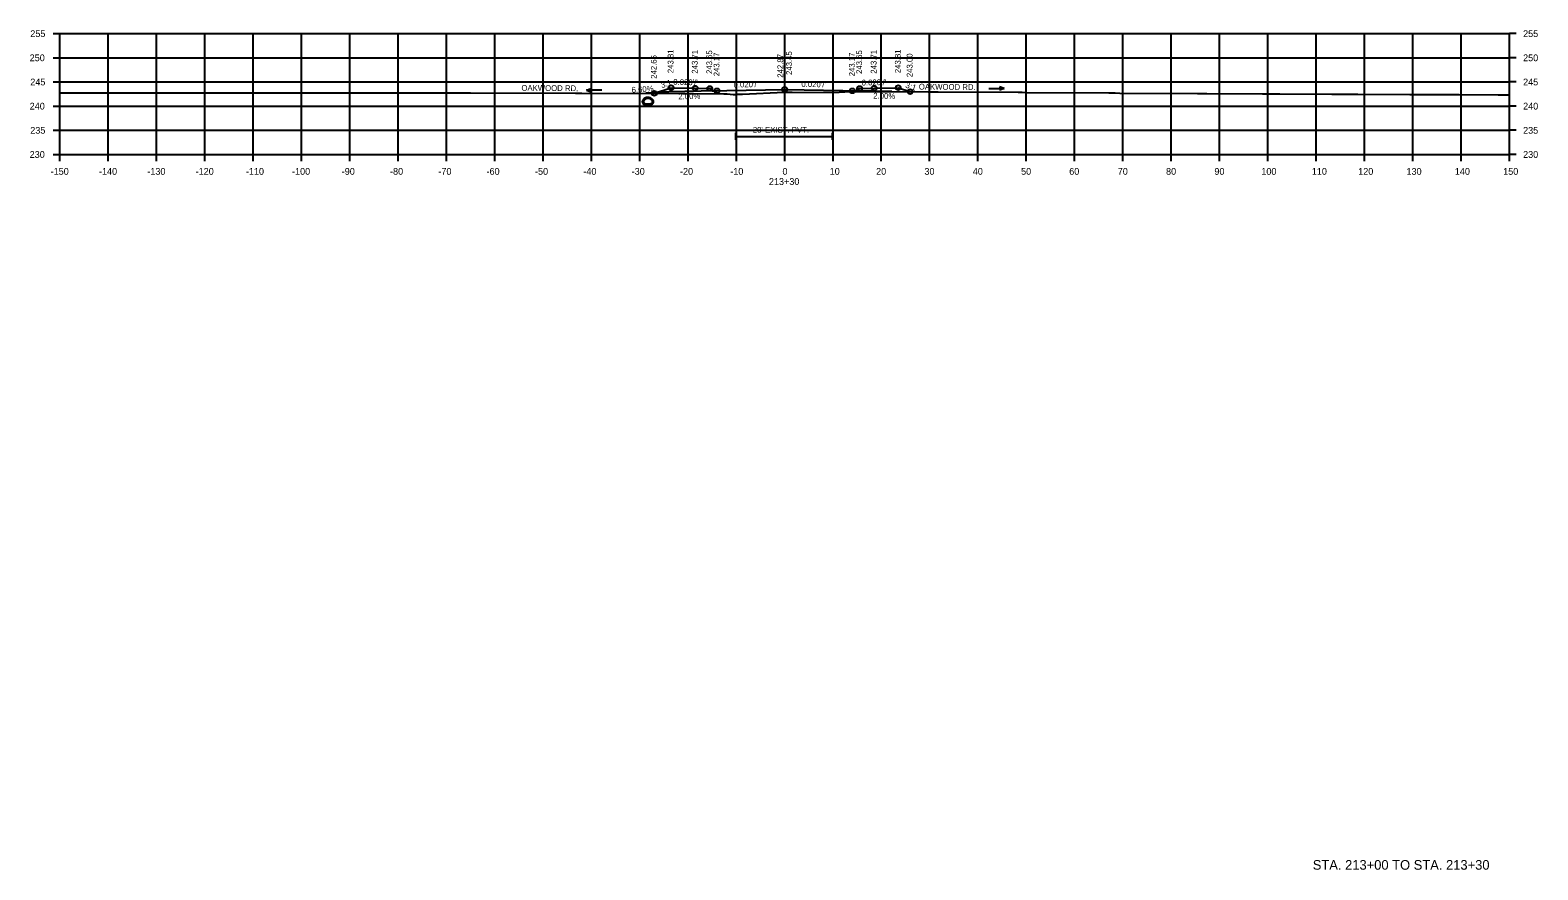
# Model space of a CAD drawing. Extents: x 1369627 to 1374022, y 380035 to 398173.
# Drawn here: x 1372730.1 to 1373042.1, y 383043.5 to 383217.3 of the extents above; entities that cross this region are included whole.
import ezdxf

# ---------------------------------------------------------------- set-up
doc = ezdxf.new("R2010")
doc.units = 0
for name, color, linetype in [('Default', 7, 'Continuous'), ('R_Alt Surface', 7, 'Continuous'), ('R_Axis', 7, 'Continuous'), ('R_Axis Annot', 7, 'Continuous'), ('R_Draft', 7, 'Continuous'), ('R_Drive', 7, 'Continuous'), ('R_Exist Surface', 7, 'Continuous'), ('R_Fin Surface', 7, 'Continuous'), ('R_Grid', 7, 'Continuous'), ('R_No Plot', 7, 'Continuous'), ('R_Water', 7, 'Continuous'), ('R_Water Annot', 7, 'Continuous'), ('R_Xsect Elev', 7, 'Continuous'), ('R_Xsect Slope', 7, 'Continuous')]:
    doc.layers.add(name, color=color, linetype=linetype)

msp = doc.modelspace()

# ---------------------------------------------------------------- linework, layer by layer
at = {"layer": 'Default'}
for p, q in [((1372876.1, 383194.57), (1372876.1, 383196.07)), ((1372876.1, 383195.32), (1372896.1, 383195.32)), ((1372896.1, 383194.57), (1372896.1, 383196.07))]:
    msp.add_line(p, q, dxfattribs=at)
at = {"layer": 'R_Axis'}
for p, q in [((1372734.81, 383216.57), (1372736.21, 383216.57)), ((1372736.21, 383191.57), (1372736.21, 383216.57)), ((1373036.21, 383191.57), (1373036.21, 383216.57)), ((1373037.61, 383216.57), (1373036.21, 383216.57)), ((1372734.81, 383211.57), (1372736.21, 383211.57)), ((1373037.61, 383211.57), (1373036.21, 383211.57)), ((1372734.81, 383206.57), (1372736.21, 383206.57)), ((1373037.61, 383206.57), (1373036.21, 383206.57)), ((1372734.81, 383201.57), (1372736.21, 383201.57)), ((1373037.61, 383201.57), (1373036.21, 383201.57)), ((1372734.81, 383196.57), (1372736.21, 383196.57)), ((1373037.61, 383196.57), (1373036.21, 383196.57)), ((1372734.81, 383191.57), (1372736.21, 383191.57)), ((1372736.21, 383191.57), (1373036.21, 383191.57)), ((1372736.21, 383190.17), (1372736.21, 383191.57)), ((1372746.21, 383190.17), (1372746.21, 383191.57)), ((1372756.21, 383190.17), (1372756.21, 383191.57)), ((1372766.21, 383190.17), (1372766.21, 383191.57)), ((1372776.21, 383190.17), (1372776.21, 383191.57)), ((1372786.21, 383190.17), (1372786.21, 383191.57)), ((1372796.21, 383190.17), (1372796.21, 383191.57)), ((1372806.21, 383190.17), (1372806.21, 383191.57)), ((1372816.21, 383190.17), (1372816.21, 383191.57)), ((1372826.21, 383190.17), (1372826.21, 383191.57)), ((1372836.21, 383190.17), (1372836.21, 383191.57)), ((1372846.21, 383190.17), (1372846.21, 383191.57)), ((1372856.21, 383190.17), (1372856.21, 383191.57)), ((1372866.21, 383190.17), (1372866.21, 383191.57)), ((1372876.21, 383190.17), (1372876.21, 383191.57)), ((1372886.21, 383190.17), (1372886.21, 383191.57)), ((1372896.21, 383190.17), (1372896.21, 383191.57)), ((1372906.21, 383190.17), (1372906.21, 383191.57)), ((1372916.21, 383190.17), (1372916.21, 383191.57)), ((1372926.21, 383190.17), (1372926.21, 383191.57)), ((1372936.21, 383190.17), (1372936.21, 383191.57)), ((1372946.21, 383190.17), (1372946.21, 383191.57)), ((1372956.21, 383190.17), (1372956.21, 383191.57)), ((1372966.21, 383190.17), (1372966.21, 383191.57)), ((1372976.21, 383190.17), (1372976.21, 383191.57)), ((1372986.21, 383190.17), (1372986.21, 383191.57)), ((1372996.21, 383190.17), (1372996.21, 383191.57)), ((1373006.21, 383190.17), (1373006.21, 383191.57)), ((1373016.21, 383190.17), (1373016.21, 383191.57)), ((1373026.21, 383190.17), (1373026.21, 383191.57)), ((1373036.21, 383190.17), (1373036.21, 383191.57)), ((1373037.61, 383191.57), (1373036.21, 383191.57))]:
    msp.add_line(p, q, dxfattribs=at)
at = {"layer": 'R_Drive'}
for p, q in [((1372862.21, 383204.55), (1372857.45, 383204.23)), ((1372872.21, 383204.75), (1372862.21, 383204.55)), ((1372908.38, 383204.58), (1372901.21, 383204.73))]:
    msp.add_line(p, q, dxfattribs=at)
at = {"layer": 'R_Exist Surface'}
msp.add_lwpolyline([(1372736.21, 383204.34), (1372738.85, 383204.34), (1372740.52, 383204.35), (1372760.34, 383204.33), (1372761.22, 383204.33), (1372761.22, 383204.33), (1372782.47, 383204.31), (1372782.51, 383204.31), (1372788.65, 383204.31), (1372801.68, 383204.32), (1372801.84, 383204.32), (1372820.79, 383204.32), (1372821.19, 383204.32), (1372842.91, 383204.26), (1372844.27, 383204.27), (1372865.07, 383204.21), (1372867.32, 383204.22), (1372873.6, 383204.1), (1372874.28, 383204.09), (1372875.53, 383203.97), (1372875.96, 383203.98), (1372876.23, 383204), (1372876.3, 383204.02), (1372877.5, 383204.07), (1372886.12, 383204.45), (1372887.79, 383204.45), (1372896.4, 383204.39), (1372899.78, 383204.61), (1372915.91, 383204.56), (1372917.54, 383204.52), (1372917.69, 383204.52), (1372917.77, 383204.52), (1372917.96, 383204.51), (1372934.56, 383204.45), (1372934.79, 383204.45), (1372935.36, 383204.44), (1372936.16, 383204.42), (1372953.32, 383204.33), (1372953.78, 383204.32), (1372954.59, 383204.3), (1372955.58, 383204.29), (1372971.61, 383204.2), (1372972.12, 383204.19), (1372972.95, 383204.18), (1372973.56, 383204.18), (1372985.11, 383204.11), (1372986.41, 383204.1), (1372988.67, 383204.1), (1372999.43, 383204.03), (1373001.12, 383204.03), (1373004.78, 383204.03), (1373015.54, 383203.99), (1373025.79, 383203.95), (1373033.88, 383203.93), (1373036.21, 383203.93)], dxfattribs=at)
at = {"layer": 'R_Fin Surface'}
msp.add_lwpolyline([(1372859.23, 383204.23), (1372862.7, 383205.39), (1372867.7, 383205.29), (1372870.7, 383205.23), (1372871.2, 383205.23), (1372871.21, 383204.73), (1372872.21, 383204.75), (1372874.21, 383204.79), (1372886.21, 383205.03), (1372898.21, 383204.79), (1372900.21, 383204.75), (1372901.21, 383204.73), (1372901.22, 383205.23), (1372901.72, 383205.23), (1372904.72, 383205.29), (1372909.72, 383205.39), (1372912.17, 383204.57)], dxfattribs=at)
at = {"layer": 'R_Grid'}
for p, q in [((1372736.21, 383216.57), (1373036.21, 383216.57)), ((1372736.21, 383191.57), (1372736.21, 383216.57)), ((1372746.21, 383191.57), (1372746.21, 383216.57)), ((1372756.21, 383191.57), (1372756.21, 383216.57)), ((1372766.21, 383191.57), (1372766.21, 383216.57)), ((1372776.21, 383191.57), (1372776.21, 383216.57)), ((1372786.21, 383191.57), (1372786.21, 383216.57)), ((1372796.21, 383191.57), (1372796.21, 383216.57)), ((1372806.21, 383191.57), (1372806.21, 383216.57)), ((1372816.21, 383191.57), (1372816.21, 383216.57)), ((1372826.21, 383191.57), (1372826.21, 383216.57)), ((1372836.21, 383191.57), (1372836.21, 383216.57)), ((1372846.21, 383191.57), (1372846.21, 383216.57)), ((1372856.21, 383191.57), (1372856.21, 383216.57)), ((1372866.21, 383191.57), (1372866.21, 383216.57)), ((1372876.21, 383191.57), (1372876.21, 383216.57)), ((1372886.21, 383191.57), (1372886.21, 383216.57)), ((1372896.21, 383191.57), (1372896.21, 383216.57)), ((1372906.21, 383191.57), (1372906.21, 383216.57)), ((1372916.21, 383191.57), (1372916.21, 383216.57)), ((1372926.21, 383191.57), (1372926.21, 383216.57)), ((1372936.21, 383191.57), (1372936.21, 383216.57)), ((1372946.21, 383191.57), (1372946.21, 383216.57)), ((1372956.21, 383191.57), (1372956.21, 383216.57)), ((1372966.21, 383191.57), (1372966.21, 383216.57)), ((1372976.21, 383191.57), (1372976.21, 383216.57)), ((1372986.21, 383191.57), (1372986.21, 383216.57)), ((1372996.21, 383191.57), (1372996.21, 383216.57)), ((1373006.21, 383191.57), (1373006.21, 383216.57)), ((1373016.21, 383191.57), (1373016.21, 383216.57)), ((1373026.21, 383191.57), (1373026.21, 383216.57)), ((1373036.21, 383191.57), (1373036.21, 383216.57)), ((1372736.21, 383211.57), (1373036.21, 383211.57)), ((1372736.21, 383206.57), (1373036.21, 383206.57)), ((1372736.21, 383201.57), (1373036.21, 383201.57)), ((1372736.21, 383196.57), (1373036.21, 383196.57)), ((1372736.21, 383191.57), (1373036.21, 383191.57))]:
    msp.add_line(p, q, dxfattribs=at)
at = {"layer": 'R_No Plot'}
for centre in [(1372859.23, 383204.23), (1372862.7, 383205.39), (1372867.7, 383205.29), (1372870.7, 383205.23), (1372872.21, 383204.75), (1372886.21, 383205.03), (1372900.21, 383204.75), (1372901.72, 383205.23), (1372904.72, 383205.29), (1372909.72, 383205.39), (1372912.17, 383204.57)]:
    msp.add_circle(centre, 0.5, dxfattribs=at)
at = {"layer": 'R_Water'}
for centre, radius, start, end in [((1372857.4, 383202.52), 0.646, 136.3515, 253.9529), ((1372857.91, 383202.03), 1.35, 43.6485, 136.3515), ((1372857.4, 383202.52), 0.438, 136.3515, 253.9529), ((1372857.91, 383202.03), 1.15, 43.6485, 136.3515), ((1372857.91, 383204.31), 2.5, 253.9529, 286.0471), ((1372857.91, 383204.31), 2.29, 253.9529, 286.0471), ((1372858.42, 383202.52), 0.438, 286.0471, 43.6485), ((1372858.42, 383202.52), 0.646, 286.0471, 43.6485)]:
    msp.add_arc(centre, radius, start, end, dxfattribs=at)
at = {"layer": 'R_Water Annot'}
for p, q in [((1372845.21, 383204.85), (1372846.17, 383205.2)), ((1372848.35, 383204.85), (1372845.21, 383204.85)), ((1372845.21, 383204.85), (1372846.17, 383204.5)), ((1372928.46, 383205.25), (1372931.6, 383205.25)), ((1372931.6, 383205.25), (1372930.64, 383205.6)), ((1372931.6, 383205.25), (1372930.64, 383204.9))]:
    msp.add_line(p, q, dxfattribs=at)
at = {"layer": 'R_Xsect Elev'}
msp.add_line((1372886.21, 383204.45), (1372886.21, 383214.45), dxfattribs=at)

# ---------------------------------------------------------------- texts
at = {"layer": 'R_Alt Surface'}
for p in [(1372831.73, 383204.75), (1372913.96, 383205)]:
    msp.add_text('OAKWOOD RD.', height=1.2, rotation=359.5795, dxfattribs=at).set_placement(p)
at = {"layer": 'R_Axis Annot'}
for s, height, p in [('255', 1.4, (1372730.1, 383215.87)), ('255', 1.4, (1373039.01, 383215.87)), ('250', 1.4, (1372729.98, 383210.87)), ('250', 1.4, (1373039.01, 383210.87)), ('245', 1.4, (1372730.1, 383205.87)), ('245', 1.4, (1373039.01, 383205.87)), ('240', 1.4, (1372729.98, 383200.87)), ('240', 1.4, (1373039.01, 383200.87)), ('235', 1.4, (1372730.1, 383195.87)), ("20' EXIST. PVT.", 1.2, (1372879.61, 383196.07)), ('235', 1.4, (1373039.01, 383195.87)), ('230', 1.4, (1372729.98, 383190.87)), ('230', 1.4, (1373039.01, 383190.87)), ('-150', 1.4, (1372734.32, 383187.37)), ('-140', 1.4, (1372744.32, 383187.37)), ('-130', 1.4, (1372754.32, 383187.37)), ('-120', 1.4, (1372764.32, 383187.37)), ('-110', 1.4, (1372774.72, 383187.37)), ('-100', 1.4, (1372784.27, 383187.37)), ('-90', 1.4, (1372794.55, 383187.37)), ('-80', 1.4, (1372804.55, 383187.37)), ('-70', 1.4, (1372814.55, 383187.37)), ('-60', 1.4, (1372824.52, 383187.37)), ('-50', 1.4, (1372834.55, 383187.37)), ('-40', 1.4, (1372844.55, 383187.37)), ('-30', 1.4, (1372854.55, 383187.37)), ('-20', 1.4, (1372864.55, 383187.37)), ('-10', 1.4, (1372874.95, 383187.37)), ('213+30', 1.4, (1372882.95, 383185.27)), ('0', 1.4, (1372885.75, 383187.37)), ('10', 1.4, (1372895.52, 383187.37)), ('20', 1.4, (1372905.13, 383187.37)), ('30', 1.4, (1372915.13, 383187.37)), ('40', 1.4, (1372925.13, 383187.37)), ('50', 1.4, (1372935.13, 383187.37)), ('60', 1.4, (1372945.09, 383187.37)), ('70', 1.4, (1372955.13, 383187.37)), ('80', 1.4, (1372965.13, 383187.37)), ('90', 1.4, (1372975.13, 383187.37)), ('100', 1.4, (1372984.84, 383187.37)), ('110', 1.4, (1372995.29, 383187.37)), ('120', 1.4, (1373004.89, 383187.37)), ('130', 1.4, (1373014.89, 383187.37)), ('140', 1.4, (1373024.89, 383187.37)), ('150', 1.4, (1373034.89, 383187.37))]:
    msp.add_text(s, height=height, dxfattribs=at).set_placement(p)
at = {"layer": 'R_Draft'}
msp.add_text('STA. 213+00 TO STA. 213+30', height=2, dxfattribs=at).set_placement((1372995.49, 383043.57))
at = {"layer": 'R_Xsect Elev'}
for s, rotation, p in [('242.65', 90, (1372859.73, 383207.23)), ('243.81', 90, (1372863.2, 383208.39)), ('243.71', 90, (1372868.2, 383208.29)), ('243.65', 90, (1372871.2, 383208.23)), ('243.17', 90, (1372872.71, 383207.75)), ('242.87', 90, (1372885.91, 383207.45)), ('243.45', 90, (1372887.71, 383208.03)), ('243.17', 90, (1372900.71, 383207.75)), ('243.65', 90, (1372902.22, 383208.23)), ('243.71', 90, (1372905.22, 383208.29)), ('243.81', 90, (1372910.22, 383208.39)), ('243.00', 90, (1372912.67, 383207.57)), ('6.60%', 3.776, (1372854.57, 383204.33)), ('2.00%', 1.1458, (1372864.22, 383202.98)), ('2.00%', 358.8542, (1372904.53, 383203.13))]:
    msp.add_text(s, height=1.2, rotation=rotation, dxfattribs=at).set_placement(p)
at = {"layer": 'R_Xsect Slope'}
for s, rotation, p in [('3:1', 18.4332, (1372860.81, 383205.28)), ("0.020'/'", 358.8542, (1372863.15, 383205.98)), ("0.020'/'", 1.1458, (1372875.64, 383205.41)), ("0.020'/'", 358.8542, (1372889.66, 383205.56)), ("0.020'/'", 1.1458, (1372902.15, 383205.83)), ('3:1', 341.5668, (1372911.1, 383205.45))]:
    msp.add_text(s, height=1.2, rotation=rotation, dxfattribs=at).set_placement(p)

doc.saveas('drawing.dxf')
